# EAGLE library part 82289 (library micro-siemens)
MICROPROCESSOR/PERIPHERAL DEVICE
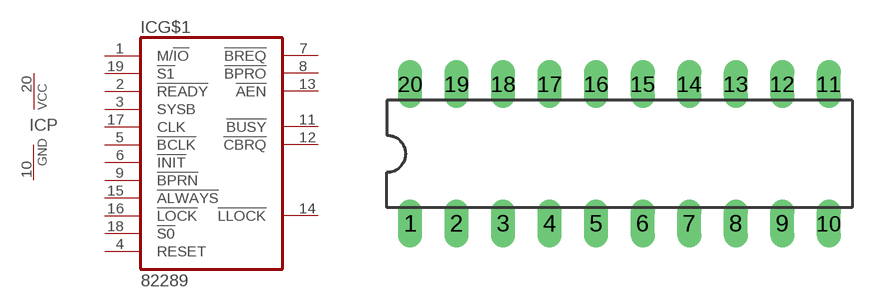
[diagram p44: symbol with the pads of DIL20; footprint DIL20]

Designator prefix IC; gates G$1=82289 P=VCCGND

## 82289 (OC_FARNELL: unknown; OC_NEWARK: unknown)  [DIL20]
1  G$1:M/!IO  in
2  G$1:!READY  in
3  G$1:SYSB  in
4  G$1:RESET  in
5  G$1:!BCLK  in
6  G$1:!INIT  in
7  G$1:!BREQ  out
8  G$1:!BPRO  out
9  G$1:!BPRN  in
10  P:GND  pwr
11  G$1:!BUSY
12  G$1:!CBRQ
13  G$1:!AEN  out
14  G$1:!LLOCK  out
15  G$1:!ALWAYS  in
16  G$1:!LOCK  in
17  G$1:CLK  in
18  G$1:!S0  in
19  G$1:!S1  in
20  P:VCC  pwr

## Footprint DIL20 (pad centres in mm)
Dual In Line Package
drill 0.813 long: 1 -11.43,-3.81; 2 -8.89,-3.81; 3 -6.35,-3.81; 4 -3.81,-3.81; 5 -1.27,-3.81; 6 1.27,-3.81; 7 3.81,-3.81; 8 6.35,-3.81; 9 8.89,-3.81; 10 11.43,-3.81; 11 11.43,3.81; 12 8.89,3.81; 13 6.35,3.81; 14 3.81,3.81; 15 1.27,3.81; 16 -1.27,3.81; 17 -3.81,3.81; 18 -6.35,3.81; 19 -8.89,3.81; 20 -11.43,3.81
